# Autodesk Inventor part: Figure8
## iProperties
Shininess: 77.0
Length Units: 11269
Angle Units: 11279
Time Units: 11290
Mass Units: 11283
Length Display Precision: 3
Angle Display Precision: 2
Compacted: True
Created: 2002-01
Part Number: Figure8
Document SubType Name: Modeling
Designer: ***
Density: 0.0
Volumn: 0.0
Area: 0.0
PropertySet Name: Model Information
Control State: 0
Master: False
Checked Out: False
Author: ***
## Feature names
1. Extrusion1
